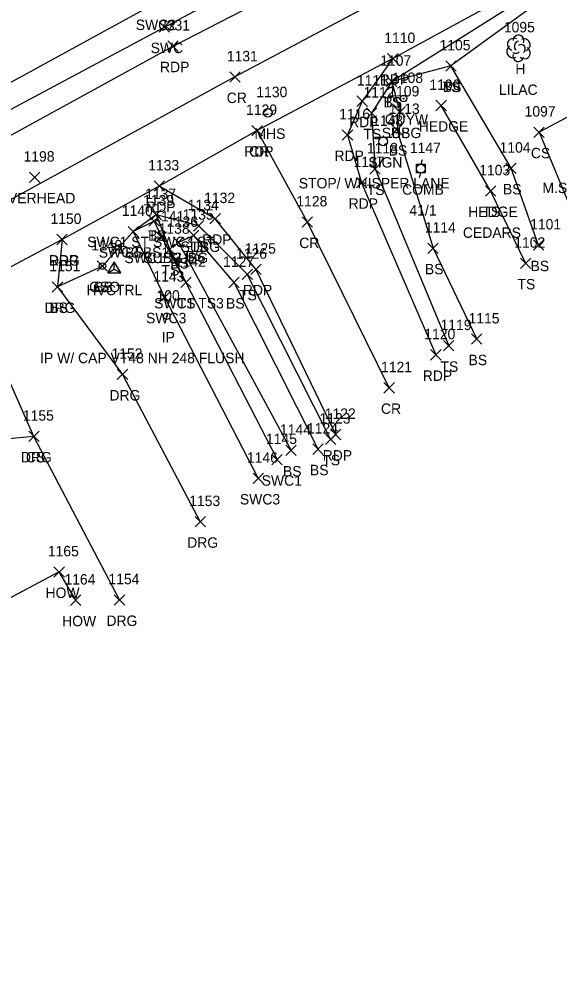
# Model space of a CAD drawing. Extents: x 1477930 to 1480780, y 774090 to 784647.
# Drawn here: x 1479765 to 1479868.7, y 774725.4 to 774907.7 of the extents above; entities that cross this region are included whole.
import ezdxf

# ---------------------------------------------------------------- set-up
doc = ezdxf.new("R2010")
doc.units = 0
for name, color, linetype in [('C_A', 7, 'Continuous'), ('C_I', 7, 'Continuous'), ('CPSM', 7, 'Continuous'), ('L_A', 7, 'Continuous'), ('L_C', 7, 'Continuous'), ('L_I', 7, 'Continuous'), ('L_TIC', 7, 'Continuous'), ('LAHR', 7, 'Continuous'), ('LBC', 7, 'Continuous'), ('LELB', 7, 'Continuous'), ('LTD', 7, 'Continuous'), ('M_A', 7, 'Continuous'), ('M_C', 7, 'Continuous'), ('M_I', 7, 'Continuous'), ('MPIR', 7, 'Continuous'), ('P_A', 7, 'Continuous'), ('P_I', 7, 'Continuous'), ('P_TIC', 7, 'Continuous'), ('PET', 7, 'Continuous'), ('PRC', 7, 'Continuous'), ('R_A', 7, 'Continuous'), ('R_I', 7, 'Continuous'), ('R_TIC', 7, 'Continuous'), ('RDG', 7, 'Continuous'), ('RSW', 7, 'Continuous'), ('S_A', 7, 'Continuous'), ('S_C', 7, 'Continuous'), ('S_I', 7, 'Continuous'), ('SSGN', 7, 'Continuous'), ('U_A', 7, 'Continuous'), ('U_C', 7, 'Continuous'), ('U_I', 7, 'Continuous'), ('U_TIC', 7, 'Continuous'), ('UGV', 7, 'Continuous'), ('UP', 7, 'Continuous'), ('UPGW', 7, 'Continuous'), ('USMH', 7, 'Continuous')]:
    doc.layers.add(name, color=color, linetype=linetype)

msp = doc.modelspace()

# ---------------------------------------------------------------- linework, layer by layer
at = {"layer": 'CPSM'}
for p, q in [((1479782.06, 774858.93), (1479783.31, 774861.1)), ((1479784.56, 774858.93), (1479783.31, 774861.1)), ((1479783.31, 774859.66), (1479783.31, 774861.1)), ((1479782.06, 774858.93), (1479783.31, 774859.66)), ((1479782.06, 774858.93), (1479784.56, 774858.93)), ((1479783.31, 774859.66), (1479783.31, 774859.66)), ((1479783.31, 774859.66), (1479784.56, 774858.93))]:
    msp.add_line(p, q, dxfattribs=at)
at = {"layer": 'L_TIC'}
for points in [[(1479846.96, 774897.65), (1479848.96, 774899.65)], [(1479848.96, 774897.65), (1479846.96, 774899.65)], [(1479846.96, 774897.65), (1479848.96, 774899.65)], [(1479848.96, 774897.65), (1479846.96, 774899.65)], [(1479835.58, 774894.69), (1479837.58, 774896.69)], [(1479837.58, 774894.69), (1479835.58, 774896.69)], [(1479835.58, 774894.69), (1479837.58, 774896.69)], [(1479837.58, 774894.69), (1479835.58, 774896.69)], [(1479845.08, 774890.06), (1479847.08, 774892.06)], [(1479847.08, 774890.06), (1479845.08, 774892.06)], [(1479831.74, 774888.6), (1479833.74, 774890.6)], [(1479833.74, 774888.6), (1479831.74, 774890.6)], [(1479837.15, 774888.81), (1479839.15, 774890.81)], [(1479839.15, 774888.81), (1479837.15, 774890.81)], [(1479836.57, 774885.45), (1479838.57, 774887.45)], [(1479838.57, 774885.45), (1479836.57, 774887.45)], [(1479863.87, 774884.94), (1479865.87, 774886.94)], [(1479865.87, 774884.94), (1479863.87, 774886.94)], [(1479832.38, 774877.89), (1479834.38, 774879.89)], [(1479834.38, 774877.89), (1479832.38, 774879.89)], [(1479858.51, 774878.02), (1479860.51, 774880.02)], [(1479860.51, 774878.02), (1479858.51, 774880.02)], [(1479854.58, 774873.67), (1479856.58, 774875.67)], [(1479856.58, 774873.67), (1479854.58, 774875.67)], [(1479854.58, 774873.67), (1479856.58, 774875.67)], [(1479856.58, 774873.67), (1479854.58, 774875.67)], [(1479790.37, 774869.12), (1479792.37, 774871.12)], [(1479792.37, 774869.12), (1479790.37, 774871.12)], [(1479790.37, 774869.12), (1479792.37, 774871.12)], [(1479792.37, 774869.12), (1479790.37, 774871.12)], [(1479785.98, 774865.88), (1479787.98, 774867.88)], [(1479787.98, 774865.88), (1479785.98, 774867.88)], [(1479798.55, 774866.97), (1479800.55, 774868.97)], [(1479800.55, 774866.97), (1479798.55, 774868.97)], [(1479797.59, 774865.15), (1479799.59, 774867.15)], [(1479799.59, 774865.15), (1479797.59, 774867.15)], [(1479792.98, 774862.45), (1479794.98, 774864.45)], [(1479794.98, 774862.45), (1479792.98, 774864.45)], [(1479794.63, 774863.79), (1479796.63, 774865.79)], [(1479796.63, 774863.79), (1479794.63, 774865.79)], [(1479843.52, 774862.68), (1479845.52, 774864.68)], [(1479845.52, 774862.68), (1479843.52, 774864.68)], [(1479863.8, 774863.28), (1479865.8, 774865.28)], [(1479865.8, 774863.28), (1479863.8, 774865.28)], [(1479780.05, 774859.26), (1479782.05, 774861.26)], [(1479782.05, 774859.26), (1479780.05, 774861.26)], [(1479861.32, 774859.78), (1479863.32, 774861.78)], [(1479863.32, 774859.78), (1479861.32, 774861.78)], [(1479807.87, 774857.68), (1479809.87, 774859.68)], [(1479809.87, 774857.68), (1479807.87, 774859.68)], [(1479771.43, 774855.26), (1479773.43, 774857.26)], [(1479773.43, 774855.26), (1479771.43, 774857.26)], [(1479796.09, 774856.13), (1479798.09, 774858.13)], [(1479798.09, 774856.13), (1479796.09, 774858.13)], [(1479805.33, 774856.1), (1479807.33, 774858.1)], [(1479807.33, 774856.1), (1479805.33, 774858.1)], [(1479846.54, 774843.97), (1479848.54, 774845.97)], [(1479848.54, 774843.97), (1479846.54, 774845.97)], [(1479851.9, 774845.24), (1479853.9, 774847.24)], [(1479853.9, 774845.24), (1479851.9, 774847.24)], [(1479766.9, 774826.58), (1479768.9, 774828.58)], [(1479768.9, 774826.58), (1479766.9, 774828.58)], [(1479823.85, 774826.03), (1479825.85, 774828.03)], [(1479825.85, 774826.03), (1479823.85, 774828.03)], [(1479821.44, 774824.12), (1479823.44, 774826.12)], [(1479823.44, 774824.12), (1479821.44, 774826.12)], [(1479816.27, 774823.88), (1479818.27, 774825.88)], [(1479818.27, 774823.88), (1479816.27, 774825.88)], [(1479771.75, 774800.56), (1479773.75, 774802.56)], [(1479773.75, 774800.56), (1479771.75, 774802.56)], [(1479774.93, 774795.14), (1479776.93, 774797.14)], [(1479776.93, 774795.14), (1479774.93, 774797.14)]]:
    msp.add_lwpolyline(points, dxfattribs=at)
at = {"layer": 'LAHR'}
msp.add_lwpolyline([(1479855.58, 774874.67), (1479846.08, 774891.06)], dxfattribs=at)
at = {"layer": 'LBC'}
msp.add_lwpolyline([(1479775.93, 774796.14), (1479772.75, 774801.56), (1479756.8, 774793.15), (1479752.98, 774800.31), (1479734.24, 774790.55)], dxfattribs=at)
at = {"layer": 'LELB'}
for points in [[(1479903.06, 774933.87), (1479899.47, 774928.71), (1479867.28, 774912.78), (1479847.96, 774898.65), (1479836.58, 774895.69), (1479832.74, 774889.6), (1479833.38, 774878.89), (1479847.54, 774844.97)], [(1479903.06, 774933.87), (1479899.1, 774930.92), (1479866.33, 774914.39), (1479836.58, 774895.69), (1479838.15, 774889.81), (1479837.57, 774886.45), (1479844.52, 774863.68), (1479852.9, 774846.24)], [(1479864.8, 774864.28), (1479859.51, 774879.02), (1479847.96, 774898.65)], [(1479888.18, 774898.27), (1479864.87, 774885.94), (1479871.52, 774870.1)], [(1479862.32, 774860.78), (1479855.58, 774874.67)], [(1479791.37, 774870.12), (1479786.98, 774866.88), (1479781.05, 774860.26), (1479772.43, 774856.26)], [(1479824.85, 774827.03), (1479808.87, 774858.68), (1479799.55, 774867.97), (1479791.37, 774870.12), (1479793.98, 774863.45), (1479797.09, 774857.13)], [(1479822.44, 774825.12), (1479806.33, 774857.1), (1479798.59, 774866.15), (1479795.63, 774864.79), (1479817.27, 774824.88)], [(1479767.9, 774827.58), (1479755.47, 774826.43), (1479737.02, 774821.5), (1479724.16, 774814.54), (1479699.51, 774793.2), (1479676.96, 774784.41), (1479668.59, 774775.62)]]:
    msp.add_lwpolyline(points, dxfattribs=at)
at = {"layer": 'LTD'}
msp.add_line((1479860.9, 774902.1), (1479860.9, 774902.1), dxfattribs=at)
msp.add_line((1479860.9, 774902.1), (1479860.9, 774902.1), dxfattribs=at)
msp.add_arc((1479860.94, 774903.53), 1.05, 335.5272, 180.9563, dxfattribs=at)
for centre, major_axis, ratio, start_param, end_param in [((1479860.1, 774902.76), (1.21, -0.51), 0.895232, 1.570796, 4.712389), ((1479860.69, 774902.56), (-0.208, -0.792), 0.645439, 3.141593, 6.283185), ((1479861.4, 774901.93), (-0.5, 0.667), 0.989748, 3.141593, 6.283185), ((1479861.94, 774902.68), (-1.14, -0.48), 0.949671, 1.570796, 4.712389), ((1479859.81, 774901.39), (0.58, -1.04), 0.959034, 3.141593, 6.283185), ((1479860.9, 774900.6), (0.26, 1.06), 0.942809, 1.570796, 4.712389), ((1479860.44, 774901.35), (-0.625, -0.083), 0.423636, 0, 3.141593), ((1479861.9, 774901.26), (-1.09, 0.79), 0.841452, 1.570796, 4.712389)]:
    msp.add_ellipse(centre, major_axis=major_axis, ratio=ratio, start_param=start_param, end_param=end_param, dxfattribs=at)
at = {"layer": 'MPIR'}
for radius in [0.625, 0.0833]:
    msp.add_circle((1479793.39, 774850.62), radius, dxfattribs=at)
at = {"layer": 'P_TIC'}
for points in [[(1479793.61, 774901.46), (1479795.61, 774903.46)], [(1479795.61, 774901.46), (1479793.61, 774903.46)], [(1479835.8, 774899.06), (1479837.8, 774901.06)], [(1479837.8, 774899.06), (1479835.8, 774901.06)], [(1479835.8, 774899.06), (1479837.8, 774901.06)], [(1479837.8, 774899.06), (1479835.8, 774901.06)], [(1479805.49, 774895.54), (1479807.49, 774897.54)], [(1479807.49, 774895.54), (1479805.49, 774897.54)], [(1479829.92, 774890.9), (1479831.92, 774892.9)], [(1479831.92, 774890.9), (1479829.92, 774892.9)], [(1479809.76, 774885.26), (1479811.76, 774887.26)], [(1479811.76, 774885.26), (1479809.76, 774887.26)], [(1479809.76, 774885.26), (1479811.76, 774887.26)], [(1479811.76, 774885.26), (1479809.76, 774887.26)], [(1479827.1, 774884.42), (1479829.1, 774886.42)], [(1479829.1, 774884.42), (1479827.1, 774886.42)], [(1479829.82, 774875.25), (1479831.82, 774877.25)], [(1479831.82, 774875.25), (1479829.82, 774877.25)], [(1479790.96, 774874.61), (1479792.96, 774876.61)], [(1479792.96, 774874.61), (1479790.96, 774876.61)], [(1479790.96, 774874.61), (1479792.96, 774876.61)], [(1479792.96, 774874.61), (1479790.96, 774876.61)], [(1479801.7, 774868.34), (1479803.7, 774870.34)], [(1479803.7, 774868.34), (1479801.7, 774870.34)], [(1479819.41, 774867.7), (1479821.41, 774869.7)], [(1479821.41, 774867.7), (1479819.41, 774869.7)], [(1479772.29, 774864.35), (1479774.29, 774866.35)], [(1479774.29, 774864.35), (1479772.29, 774866.35)], [(1479809.53, 774858.64), (1479811.53, 774860.64)], [(1479811.53, 774858.64), (1479809.53, 774860.64)], [(1479844.06, 774842.22), (1479846.06, 774844.22)], [(1479846.06, 774842.22), (1479844.06, 774844.22)], [(1479835.1, 774835.89), (1479837.1, 774837.89)], [(1479837.1, 774835.89), (1479835.1, 774837.89)], [(1479824.85, 774826.94), (1479826.85, 774828.94)], [(1479826.85, 774826.94), (1479824.85, 774828.94)]]:
    msp.add_lwpolyline(points, dxfattribs=at)
at = {"layer": 'PET'}
for points in [[(1479458.85, 774725.87), (1479463.75, 774725.49), (1479503.78, 774746.04), (1479529.26, 774759.88), (1479547.26, 774769.69), (1479593.15, 774794.19), (1479638.49, 774817.33), (1479672.22, 774835.12), (1479713.57, 774857.96), (1479753.19, 774879.74), (1479794.61, 774902.46), (1479830.33, 774920.88), (1479861.74, 774937.83), (1479877.76, 774946.85), (1479905.13, 774960.92), (1479936.65, 774977.61), (1479958.81, 774989.4), (1479973, 774995.93), (1480008.35, 775014.95)], [(1480020.8, 774996.12), (1479976.43, 774973.17), (1479932.79, 774950.42), (1479923.24, 774944.9), (1479898.9, 774932.87), (1479865.62, 774915.8), (1479836.8, 774900.06), (1479810.76, 774886.26), (1479791.96, 774875.61), (1479773.29, 774865.35), (1479751.05, 774853.49), (1479713.99, 774833.47), (1479663.95, 774806)], [(1479836.8, 774900.06), (1479830.92, 774891.9), (1479828.1, 774885.42), (1479830.82, 774876.25), (1479845.06, 774843.22)], [(1479825.85, 774827.94), (1479810.53, 774859.64), (1479802.7, 774869.34), (1479791.96, 774875.61)]]:
    msp.add_lwpolyline(points, dxfattribs=at)
at = {"layer": 'PRC'}
for points in [[(1480015.89, 775005.87), (1479971.79, 774982.46), (1479929.14, 774959.03), (1479892.61, 774942.34), (1479860.44, 774925.31), (1479806.49, 774896.54), (1479658.45, 774815.54), (1479643.75, 774807.57), (1479597.62, 774782.97), (1479555.61, 774761.16), (1479513.42, 774740.32), (1479471, 774718.6), (1479432.73, 774701.1), (1479418.32, 774694.97), (1479344.83, 774660.92), (1479298.6, 774640.39), (1479262.12, 774624.4), (1479219.63, 774609.01), (1479186.74, 774593.83)], [(1479836.1, 774836.89), (1479820.41, 774868.7), (1479810.76, 774886.26)]]:
    msp.add_lwpolyline(points, dxfattribs=at)
at = {"layer": 'R_TIC'}
for points in [[(1479791.95, 774905.12), (1479793.95, 774907.12)], [(1479793.95, 774905.12), (1479791.95, 774907.12)], [(1479789.99, 774867.89), (1479791.99, 774869.89)], [(1479791.99, 774867.89), (1479789.99, 774869.89)], [(1479789.99, 774867.89), (1479791.99, 774869.89)], [(1479791.99, 774867.89), (1479789.99, 774869.89)], [(1479785.98, 774865.88), (1479787.98, 774867.88)], [(1479787.98, 774865.88), (1479785.98, 774867.88)], [(1479772.29, 774864.35), (1479774.29, 774866.35)], [(1479774.29, 774864.35), (1479772.29, 774866.35)], [(1479791.38, 774864.82), (1479793.38, 774866.82)], [(1479793.38, 774864.82), (1479791.38, 774866.82)], [(1479771.43, 774855.26), (1479773.43, 774857.26)], [(1479773.43, 774855.26), (1479771.43, 774857.26)], [(1479796.09, 774856.13), (1479798.09, 774858.13)], [(1479798.09, 774856.13), (1479796.09, 774858.13)], [(1479791.96, 774853.28), (1479793.96, 774855.28)], [(1479793.96, 774853.28), (1479791.96, 774855.28)], [(1479783.91, 774838.46), (1479785.91, 774840.46)], [(1479785.91, 774838.46), (1479783.91, 774840.46)], [(1479766.9, 774826.58), (1479768.9, 774828.58)], [(1479768.9, 774826.58), (1479766.9, 774828.58)], [(1479813.58, 774822.11), (1479815.58, 774824.11)], [(1479815.58, 774822.11), (1479813.58, 774824.11)], [(1479809.97, 774818.51), (1479811.97, 774820.51)], [(1479811.97, 774818.51), (1479809.97, 774820.51)], [(1479798.83, 774810.2), (1479800.83, 774812.2)], [(1479800.83, 774810.2), (1479798.83, 774812.2)], [(1479783.33, 774795.2), (1479785.33, 774797.2)], [(1479785.33, 774795.2), (1479783.33, 774797.2)]]:
    msp.add_lwpolyline(points, dxfattribs=at)
at = {"layer": 'RDG'}
for points in [[(1479773.29, 774865.35), (1479772.43, 774856.26), (1479784.91, 774839.46), (1479799.83, 774811.2)], [(1479784.33, 774796.2), (1479767.9, 774827.58), (1479759.78, 774845.84)]]:
    msp.add_lwpolyline(points, dxfattribs=at)
at = {"layer": 'RSW'}
for points in [[(1479454.05, 774732.2), (1479457.36, 774735.51), (1479461.55, 774734.41), (1479499.97, 774753.7), (1479531.62, 774770.46), (1479545.78, 774777.94), (1479596.7, 774804.86), (1479626.34, 774821.05), (1479665.84, 774842.34), (1479709.72, 774866.29), (1479748.23, 774887.23), (1479790.98, 774910.55), (1479825.88, 774929.42), (1479857.89, 774946.35), (1479880.81, 774958.36), (1479898.02, 774967.81), (1479932.31, 774985.56), (1479966.42, 775003.67), (1480005.03, 775023.74)], [(1479458.85, 774725.87), (1479459.6, 774730), (1479502.04, 774749.23), (1479530.65, 774764.31), (1479546.64, 774772.58), (1479592.5, 774796.78), (1479632.83, 774818.63), (1479668.4, 774838.36), (1479711.89, 774862.21), (1479750.54, 774883.44), (1479792.95, 774906.12), (1479828.15, 774924.96), (1479859.81, 774941.82), (1479882.29, 774953.43), (1479899.45, 774962.93), (1479935.39, 774981.77), (1479958.84, 774993.68), (1479967.68, 774998.52), (1480006.53, 775018.83)], [(1479790.99, 774868.89), (1479786.98, 774866.88), (1479792.96, 774854.28), (1479810.97, 774819.51)], [(1479790.99, 774868.89), (1479792.38, 774865.82), (1479797.09, 774857.13), (1479814.58, 774823.11)]]:
    msp.add_lwpolyline(points, dxfattribs=at)
at = {"layer": 'SSGN'}
for p, q in [((1479833.32, 774885.01), (1479836.65, 774885.01)), ((1479834.96, 774884.18), (1479834.96, 774884.18))]:
    msp.add_line(p, q, dxfattribs=at)
msp.add_circle((1479834.96, 774884.18), 0.833, dxfattribs=at)
at = {"layer": 'U_TIC'}
for points in [[(1479837.15, 774888.81), (1479839.15, 774890.81)], [(1479839.15, 774888.81), (1479837.15, 774890.81)], [(1479767.03, 774876.3), (1479769.03, 774878.3)], [(1479769.03, 774876.3), (1479767.03, 774878.3)], [(1479798.55, 774866.97), (1479800.55, 774868.97)], [(1479800.55, 774866.97), (1479798.55, 774868.97)], [(1479791.38, 774864.82), (1479793.38, 774866.82)], [(1479793.38, 774864.82), (1479791.38, 774866.82)]]:
    msp.add_lwpolyline(points, dxfattribs=at)
at = {"layer": 'UGV'}
for radius in [0.625, 0.0833]:
    msp.add_circle((1479781.05, 774860.26), radius, dxfattribs=at)
at = {"layer": 'UP'}
for p, q in [((1479842.44, 774880.62), (1479842.19, 774879.78)), ((1479841.36, 774878.12), (1479841.36, 774879.78)), ((1479841.36, 774879.78), (1479843.03, 774879.78)), ((1479842.19, 774878.95), (1479842.19, 774878.95)), ((1479843.03, 774879.78), (1479843.03, 774878.12)), ((1479843.03, 774878.12), (1479841.36, 774878.12)), ((1479841.94, 774877.28), (1479842.19, 774878.12))]:
    msp.add_line(p, q, dxfattribs=at)
msp.add_circle((1479842.19, 774878.95), 0.833, dxfattribs=at)
at = {"layer": 'UPGW'}
for radius in [0.625, 0.0833]:
    msp.add_circle((1479838.87, 774892.39), radius, dxfattribs=at)
at = {"layer": 'USMH'}
for p, q in [((1479812.81, 774889.66), (1479812.81, 774889.66)), ((1479813.65, 774889.66), (1479813.65, 774889.66))]:
    msp.add_line(p, q, dxfattribs=at)
msp.add_circle((1479812.81, 774889.66), 0.833, dxfattribs=at)

# ---------------------------------------------------------------- texts
at = {"layer": 'C_A'}
msp.add_text('HVCTRL', height=2, dxfattribs=at).set_placement((1479778, 774854.66))
at = {"layer": 'C_I'}
msp.add_text('21', height=2, dxfattribs=at).set_placement((1479782.41, 774862.66))
at = {"layer": 'L_A'}
for s, p in [('H', (1479860.33, 774897.1)), ('TS', (1479846.37, 774893.65)), ('BS', (1479846.4, 774893.65)), ('TS', (1479834.99, 774890.69)), ('BS', (1479835.02, 774890.69)), ('HEDGE', (1479841.78, 774886.06)), ('TS', (1479831.15, 774884.6)), ('BS', (1479836.59, 774884.81)), ('BS', (1479836.01, 774881.45)), ('CS', (1479863.31, 774880.94)), ('TS', (1479831.79, 774873.89)), ('BS', (1479857.95, 774874.02)), ('HEDGE', (1479851.28, 774869.67)), ('TS', (1479853.99, 774869.67)), ('TS', (1479789.78, 774865.12)), ('BS', (1479789.81, 774865.12)), ('TS', (1479797.96, 774862.97)), ('BS', (1479785.43, 774861.88)), ('BS', (1479797.03, 774861.15)), ('BS', (1479794.08, 774859.79)), ('BS', (1479842.96, 774858.68)), ('BS', (1479863.24, 774859.28)), ('TS', (1479792.39, 774858.45)), ('BS', (1479779.49, 774855.26)), ('TS', (1479860.73, 774855.78)), ('TS', (1479807.28, 774853.68)), ('BS', (1479770.87, 774851.26)), ('TS', (1479795.5, 774852.13)), ('BS', (1479804.77, 774852.1)), ('BS', (1479851.34, 774841.24)), ('TS', (1479845.95, 774839.97)), ('CS', (1479766.34, 774822.58)), ('TS', (1479823.26, 774822.03)), ('BS', (1479815.71, 774819.88)), ('BS', (1479820.89, 774820.12)), ('HOW', (1479770.13, 774796.56)), ('HOW', (1479773.31, 774791.14))]:
    msp.add_text(s, height=2, dxfattribs=at).set_placement(p)
at = {"layer": 'L_C'}
for s, p in [('LILAC', (1479857.17, 774893.1)), ('M.SPRUC', (1479865.53, 774874.26)), ('CEDARS', (1479850.26, 774865.67))]:
    msp.add_text(s, height=2, dxfattribs=at).set_placement(p)
at = {"layer": 'L_I'}
for s, p in [('1095', (1479858.12, 774905.1)), ('1105', (1479845.76, 774901.65)), ('1105', (1479845.76, 774901.65)), ('1107', (1479834.38, 774898.69)), ('1107', (1479834.38, 774898.69)), ('1106', (1479843.82, 774894.06)), ('1112', (1479831.18, 774892.6)), ('1109', (1479835.94, 774892.81)), ('1113', (1479836.01, 774889.45)), ('1097', (1479862.1, 774888.94)), ('1118', (1479831.82, 774881.89)), ('1104', (1479857.3, 774882.02)), ('1103', (1479853.38, 774877.67)), ('1103', (1479853.38, 774877.67)), ('1137', (1479789.25, 774873.12)), ('1137', (1479789.25, 774873.12)), ('1140', (1479784.77, 774869.88)), ('1134', (1479797.42, 774870.97)), ('1136', (1479793.45, 774867.79)), ('1135', (1479796.46, 774869.15)), ('1138', (1479791.85, 774866.45)), ('1114', (1479842.96, 774866.68)), ('1101', (1479863.16, 774867.28)), ('1149', (1479778.91, 774863.26)), ('1102', (1479860.12, 774863.78)), ('1126', (1479806.69, 774861.68)), ('1151', (1479770.87, 774859.26)), ('1142', (1479794.96, 774860.13)), ('1127', (1479804.21, 774860.1)), ('1119', (1479845.97, 774847.97)), ('1115', (1479851.34, 774849.24)), ('1155', (1479765.78, 774830.58)), ('1123', (1479822.72, 774830.03)), ('1144', (1479815.14, 774827.88)), ('1124', (1479820.32, 774828.12)), ('1165', (1479770.57, 774804.56)), ('1164', (1479773.76, 774799.14))]:
    msp.add_text(s, height=2, dxfattribs=at).set_placement(p)
at = {"layer": 'M_A'}
msp.add_text('IP', height=2, dxfattribs=at).set_placement((1479792.44, 774845.62))
at = {"layer": 'M_C'}
msp.add_text('IP W/ CAP VT48 NH 248 FLUSH', height=2, dxfattribs=at).set_placement((1479769.09, 774841.62))
at = {"layer": 'M_I'}
msp.add_text('100', height=2, dxfattribs=at).set_placement((1479791.43, 774853.62))
at = {"layer": 'P_A'}
for s, p in [('RDP', (1479792.1, 774897.46)), ('RDP', (1479834.29, 774895.06)), ('RDP', (1479834.29, 774895.06)), ('CR', (1479804.92, 774891.54)), ('RDP', (1479828.4, 774886.9)), ('RDP', (1479808.25, 774881.26)), ('CR', (1479809.2, 774881.26)), ('RDP', (1479825.59, 774880.42)), ('RDP', (1479789.45, 774870.61)), ('RDP', (1479789.45, 774870.61)), ('RDP', (1479828.31, 774871.25)), ('RDP', (1479800.19, 774864.34)), ('CR', (1479818.84, 774863.7)), ('RDP', (1479770.77, 774860.35)), ('RDP', (1479808.01, 774854.64)), ('RDP', (1479842.55, 774838.22)), ('CR', (1479834.53, 774831.89)), ('RDP', (1479823.34, 774822.94))]:
    msp.add_text(s, height=2, dxfattribs=at).set_placement(p)
at = {"layer": 'P_I'}
for s, p in [('3331', (1479791.92, 774905.46)), ('1110', (1479835.16, 774903.06)), ('1110', (1479835.16, 774903.06)), ('1131', (1479804.93, 774899.54)), ('1111', (1479829.92, 774894.9)), ('1129', (1479808.63, 774889.26)), ('1129', (1479808.63, 774889.26)), ('1116', (1479826.49, 774888.42)), ('1133', (1479789.83, 774878.61)), ('1133', (1479789.83, 774878.61)), ('1117', (1479829.26, 774879.25)), ('1132', (1479800.57, 774872.34)), ('1128', (1479818.28, 774871.7)), ('1150', (1479771.07, 774868.35)), ('1125', (1479808.4, 774862.64)), ('1120', (1479842.85, 774846.22)), ('1121', (1479834.54, 774839.89)), ('1122', (1479823.73, 774830.94))]:
    msp.add_text(s, height=2, dxfattribs=at).set_placement(p)
at = {"layer": 'R_A'}
for s, p in [('SWC2', (1479787.45, 774905.55)), ('SWC', (1479790.31, 774901.12)), ('SWC1 ST SWC3 ST', (1479778.12, 774863.89)), ('SWC1 ST SWC3 ST', (1479778.12, 774863.89)), ('DRG', (1479770.77, 774860.35)), ('SWC3 BS1', (1479780.34, 774861.88)), ('SWC1 SUBG', (1479785.29, 774860.82)), ('DRG', (1479769.92, 774851.26)), ('SWC1 TS3', (1479790.98, 774852.13)), ('SWC3', (1479789.43, 774849.28)), ('DRG', (1479782.4, 774834.46)), ('DRG', (1479765.39, 774822.58)), ('SWC1', (1479811.62, 774818.11)), ('SWC3', (1479807.44, 774814.51)), ('DRG', (1479797.32, 774806.2)), ('DRG', (1479781.82, 774791.2))]:
    msp.add_text(s, height=2, dxfattribs=at).set_placement(p)
at = {"layer": 'R_I'}
for s, p in [('1139', (1479788.86, 774871.89)), ('1139', (1479788.86, 774871.89)), ('1140', (1479784.77, 774869.88)), ('1150', (1479771.07, 774868.35)), ('1141', (1479790.82, 774868.82)), ('1151', (1479770.87, 774859.26)), ('1142', (1479794.96, 774860.13)), ('1143', (1479790.83, 774857.28)), ('1152', (1479782.78, 774842.46)), ('1155', (1479765.78, 774830.58)), ('1145', (1479812.45, 774826.11)), ('1146', (1479808.79, 774822.51)), ('1153', (1479797.71, 774814.2)), ('1154', (1479782.2, 774799.2))]:
    msp.add_text(s, height=2, dxfattribs=at).set_placement(p)
at = {"layer": 'S_A'}
msp.add_text('SIGN', height=2, dxfattribs=at).set_placement((1479832.1, 774879.16))
at = {"layer": 'S_C'}
msp.add_text('STOP/ WHISPER LANE', height=2, dxfattribs=at).set_placement((1479818.74, 774875.16))
at = {"layer": 'S_I'}
msp.add_text('1148', height=2, dxfattribs=at).set_placement((1479832.82, 774887.16))
at = {"layer": 'U_A'}
for s, p in [('GUYW', (1479835.26, 774887.39)), ('MHS', (1479810.23, 774884.66)), ('SUBG', (1479834.68, 774884.81)), ('COMB', (1479838.58, 774873.95)), ('OVERHEAD', (1479760.84, 774872.3)), ('SUBG', (1479796.07, 774862.97)), ('SUBG', (1479788.91, 774860.82)), ('GSO', (1479778.5, 774855.26))]:
    msp.add_text(s, height=2, dxfattribs=at).set_placement(p)
at = {"layer": 'U_C'}
msp.add_text('41/1', height=2, dxfattribs=at).set_placement((1479839.99, 774869.95))
at = {"layer": 'U_I'}
for s, p in [('1108', (1479836.66, 774895.39)), ('1130', (1479810.6, 774892.66)), ('1109', (1479835.94, 774892.81)), ('1147', (1479840.07, 774881.95)), ('1198', (1479765.91, 774880.3)), ('1134', (1479797.42, 774870.97)), ('1141', (1479790.82, 774868.82)), ('1149', (1479778.91, 774863.26))]:
    msp.add_text(s, height=2, dxfattribs=at).set_placement(p)

doc.saveas('drawing.dxf')
